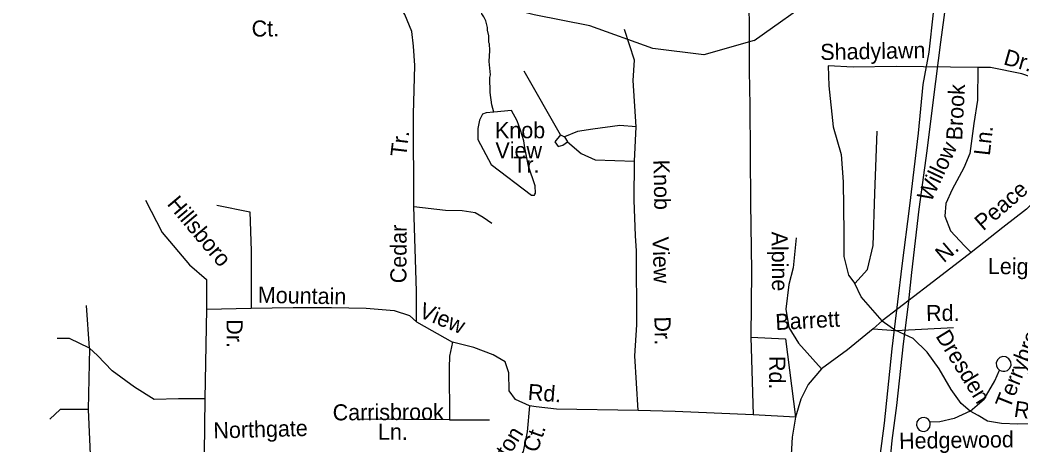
# Model space of a CAD drawing. Extents: x 1547597 to 1699558, y 810033 to 920809.
# Drawn here: x 1600245 to 1606161, y 855999 to 858511 of the extents above; entities that cross this region are included whole.
import ezdxf

# ---------------------------------------------------------------- set-up
doc = ezdxf.new("R2010")
doc.units = 0
for name, color, linetype in [('Exist Hydrographic Misc Water Feature', 7, 'Continuous'), ('Exist Road Non-System Type 51', 7, 'Continuous'), ('Exist Road Non-System Type 51 Label', 7, 'Continuous'), ('Exist Utilities Electrical Transmission Line', 7, 'Continuous')]:
    doc.layers.add(name, color=color, linetype=linetype)

msp = doc.modelspace()

# ---------------------------------------------------------------- linework, layer by layer
at = {"layer": 'Exist Hydrographic Misc Water Feature'}
for points in [[(1604584.3, 858390.6), (1604287.2, 858305.2), (1603985.1, 858343), (1603612.2, 858475.9), (1603283.5, 858542.3), (1603061.6, 858597.4), (1602912.6, 858649.7), (1602822.6, 858766.3), (1602649.1, 858955.8), (1602559.2, 859056.1), (1602486.9, 859102.3), (1602189.8, 859143.4), (1601995.6, 859301.8), (1601795.6, 859312.4), (1601299.5, 858990.5), (1600990.4, 858944.3), (1600488.8, 858943), (1600013.3, 858958.8), (1599039.8, 858996.7), (1598638.6, 858913.6)], [(1604584.3, 858390.6), (1604956.1, 858655.5), (1605784.2, 858699.8), (1606209.7, 858996.3)], [(1603044.7, 857966.8), (1603034.4, 858010.4), (1603023.4, 858082.5), (1603022.5, 858170.5), (1603024.8, 858186.4), (1603017.9, 858266.5), (1603020.8, 858330.5), (1603019.4, 858370.5), (1603015.5, 858378.5), (1603016, 858418.5), (1603008.4, 858450.6), (1603008.6, 858466.6), (1602997.2, 858506.8), (1602985.5, 858530.9), (1602973.7, 858547.1), (1602971.9, 858555.1), (1602912.6, 858649.7)], [(1603044.7, 857966.8), (1602999.4, 857962.8), (1602977.9, 857955.6), (1602960.2, 857918.7), (1602949.8, 857869.4), (1602949.9, 857804.2), (1603029.8, 857656.6), (1603267.6, 857476.7), (1603284.9, 857475.6), (1603287.7, 857481)], [(1603287.7, 857481), (1603290.9, 857487.1), (1603289.6, 857531.7), (1603249.7, 857647.5), (1603227.8, 857754.9), (1603221.7, 857797), (1603203.4, 857860.7), (1603182.6, 857916.2), (1603150.3, 857975.9), (1603044.7, 857966.8)]]:
    msp.add_lwpolyline(points, dxfattribs=at)
at = {"layer": 'Exist Road Non-System Type 51'}
for points in [[(1604523.8, 858949.4), (1604554.7, 858810.2), (1604551.3, 858642.4), (1604554.7, 858426.7), (1604554.7, 858211), (1604558.1, 858005.6), (1604561.4, 857430.5), (1604568.2, 857026.5), (1604564.6, 856637.2)], [(1602573.3, 857409.5), (1602570.3, 857954.4), (1602579.2, 858242.1), (1602570.3, 858356.4), (1602561.4, 858442.4), (1602519.9, 858543.3), (1602448.8, 858667.9), (1602410.3, 858724.2), (1602389.3, 858797.1)], [(1603885.6, 857879), (1603869.2, 858153.3), (1603877.4, 858274.1), (1603817.1, 858455.1)], [(1605021.5, 858240.6), (1605024.5, 858121.7), (1605049.7, 857879.1), (1605097.7, 857717.3), (1605110.3, 857555.6), (1605112.9, 857252.3), (1605112.9, 857112.6), (1605140.6, 857003.9), (1605178.6, 856953.3)], [(1605905.4, 858230.5), (1605423, 858235.6), (1605168, 858233), (1605021.5, 858240.6)], [(1605905.4, 858230.5), (1605902.8, 858038.4), (1605882.6, 857899.4), (1605857.4, 857722.5), (1605822, 857636.6), (1605753.8, 857510.2), (1605716, 857426.8), (1605710.9, 857351), (1605743.7, 857265.8), (1605827.1, 857177.4), (1605866.7, 857136.9)], [(1606563.5, 858048.4), (1606410.4, 858109.2), (1606165.5, 858192.6), (1605981.1, 858230.5), (1605905.4, 858230.5)], [(1603438.8, 857832.4), (1603225, 858208.2)], [(1603885.6, 857879), (1603789.7, 857887.2), (1603630.7, 857865.3), (1603540.2, 857851.6), (1603463.5, 857821.4)], [(1603877.5, 857677), (1603885.6, 857879)], [(1603438.8, 857832.4), (1603405.9, 857791.2), (1603425.1, 857763.8), (1603452.5, 857772), (1603479.9, 857791.2)], [(1603438.8, 857832.4), (1603463.5, 857821.4)], [(1603463.5, 857821.4), (1603479.9, 857791.2)], [(1605178.6, 856953.3), (1605254.3, 857036.7), (1605287.2, 857178.3), (1605297.3, 857486.6), (1605309.8, 857853.8)], [(1603479.9, 857791.2), (1603562.1, 857722.6), (1603644.4, 857684.2), (1603877.5, 857677)], [(1606429.7, 857727.4), (1606369, 857598.5), (1606285.7, 857484.8), (1606192.3, 857393.8), (1606053.4, 857285.1), (1605866.7, 857136.9)], [(1603898.5, 856203.6), (1603877.6, 856526.1), (1603891.3, 856709.9), (1603888.6, 857146.1), (1603883, 857235.3), (1603874.8, 857446.6), (1603877.5, 857677)], [(1600986.1, 857446.8), (1601086.1, 857255.3), (1601246.9, 857063.9), (1601346.9, 856976.9), (1601346.9, 856802.9)], [(1601407.8, 857416.3), (1601603.4, 857377.2), (1601612.1, 857146.6), (1601612.1, 856968.2), (1601612.1, 856807.3)], [(1602573.3, 857409.5), (1602758.8, 857388.1), (1602858.6, 857386.2), (1602934.4, 857372.7), (1602981.9, 857345.9), (1603033.2, 857311.1)], [(1602588.9, 856727.3), (1602588.1, 856908.3), (1602573.3, 857409.5)], [(1604832.5, 857223.8), (1604814.9, 857046.9), (1604789.6, 856948.3), (1604771.9, 856801.7), (1604789.6, 856693.1), (1604845.2, 856602.1), (1604981.5, 856450.4)], [(1605866.7, 857136.9), (1605617.9, 856945.8), (1605340.2, 856733.5)], [(1605340.2, 856733.5), (1605216.5, 856875), (1605178.6, 856953.3)], [(1600655.8, 856572.4), (1600638.4, 856824.7)], [(1601346.9, 856802.9), (1601338.2, 856272.2)], [(1601346.9, 856802.9), (1601612.1, 856807.3)], [(1601612.1, 856807.3), (1601859.8, 856811.6), (1602085.9, 856811.6), (1602290.2, 856807.3), (1602455.3, 856794.2), (1602546.6, 856763.8), (1602588.9, 856727.3)], [(1602588.9, 856727.3), (1602801.2, 856607)], [(1605287.2, 856685.4), (1605135.6, 856561.6), (1604981.5, 856450.4)], [(1605340.2, 856733.5), (1605287.2, 856685.4)], [(1605287.2, 856685.4), (1605421, 856675.3)], [(1605340.2, 856733.5), (1605421, 856675.3)], [(1605421, 856675.3), (1605761.9, 856693)], [(1600655.8, 856572.4), (1600538.4, 856628.9), (1600464.5, 856628.9)], [(1604564.6, 856637.2), (1604578.3, 856178.4)], [(1604564.6, 856637.2), (1604769.9, 856626.9)], [(1604769.9, 856626.9), (1604828.1, 856164.7)], [(1605859.4, 856198.9), (1605806.4, 856244.4), (1605748.3, 856327.8), (1605677.6, 856449.1), (1605606.9, 856547.7), (1605523.5, 856628.5), (1605421, 856675.3)], [(1600655.8, 856572.4), (1600647.8, 856208.1)], [(1601338.2, 856272.2), (1601181.7, 856272.2), (1601038.3, 856267.9), (1600920.9, 856341.8), (1600790.5, 856437.5), (1600703.6, 856528.9), (1600655.8, 856572.4)], [(1602801.2, 856607), (1602784.1, 856524.8), (1602780.7, 856456.3)], [(1603255.4, 856231), (1603174.1, 856268), (1603136.5, 856319.4), (1603133, 856425.5), (1603112.5, 856490.6), (1603040.7, 856531.6), (1602927.8, 856576.2), (1602801.2, 856607)], [(1606054.3, 856434.9), (1606065.3, 856435.2), (1606080.6, 856440.1), (1606093.9, 856453.3), (1606101.7, 856470.5), (1606100.5, 856490), (1606088.6, 856509.2), (1606071.8, 856519.8), (1606053.7, 856521.5), (1606035.9, 856515.7), (1606022.3, 856502.2), (1606014.1, 856485.9), (1606016.3, 856464.9), (1606023.6, 856450.9), (1606034.6, 856441.1), (1606043.9, 856436.7), (1606054.3, 856434.9)], [(1602780.7, 856456.3), (1602784.1, 856148.2)], [(1604981.5, 856450.4), (1604903.3, 856356.5), (1604858.8, 856270.9), (1604828.1, 856164.7)], [(1605859.4, 856198.9), (1605942.7, 856269.7), (1606005.9, 856378.3), (1606034.6, 856441.1)], [(1601338.2, 856272.2), (1601333.9, 855950.3)], [(1600647.8, 856208.1), (1600482.7, 856208.1), (1600421.8, 856151.6)], [(1600647.8, 856208.1), (1600660.9, 855899.3)], [(1603255.4, 856231), (1603241.7, 856076.9), (1603217.8, 855960.5), (1603125.4, 855803), (1603070.7, 855720.9)], [(1603898.5, 856203.6), (1603416.2, 856210.4), (1603296.4, 856224.1), (1603255.4, 856231)], [(1602784.1, 856148.2), (1602253.9, 856151.6)], [(1602784.1, 856148.2), (1603020.2, 856148.2)], [(1604116.2, 856197), (1603898.5, 856203.6)], [(1604578.3, 856178.4), (1604116.2, 856197)], [(1604828.1, 856164.7), (1604578.3, 856178.4)], [(1604828.1, 856164.7), (1604807.5, 856044.9), (1604800.7, 855908), (1604793.8, 855805.3), (1604779.6, 855729.1)], [(1605624.8, 856122.6), (1605623.8, 856133.3), (1605614.1, 856150.1), (1605601.7, 856158.7), (1605588.8, 856162.2), (1605571.9, 856160.3), (1605556.3, 856152.3), (1605545.2, 856136.3), (1605542.6, 856117.1), (1605548.1, 856101.6), (1605559.8, 856087.9), (1605574.3, 856081.2), (1605589.7, 856079.9), (1605608.7, 856087.8), (1605621.4, 856104.1), (1605624.8, 856122.6)], [(1605859.4, 856198.9), (1605766, 856155.9), (1605680.1, 856135.7), (1605623.8, 856133.3)], [(1606483.2, 856120.8), (1606314, 856125.6), (1606142.2, 856123.1), (1606046.3, 856125.6), (1605962.9, 856140.8), (1605907.4, 856173.6), (1605859.4, 856198.9)]]:
    msp.add_lwpolyline(points, dxfattribs=at)
at = {"layer": 'Exist Utilities Electrical Transmission Line'}
for points in [[(1606188.9, 862441.7), (1606114.6, 862291), (1606083.3, 862079.7), (1606035.2, 861688.6), (1605980.2, 861255.7), (1605918.3, 860753.1), (1605862.5, 860386.2), (1605838.3, 860120.8), (1605807.3, 859925.3), (1605778.9, 859647.9), (1605735, 859282.8), (1605693.8, 858949.6), (1605641.6, 858552.9), (1605615.9, 858321.3), (1605581, 858130.1), (1605552.3, 857842.7), (1605501.6, 857413.7), (1605456, 857058.6), (1605430.6, 856845.2), (1605398.2, 856567.9), (1605351.3, 856128.8), (1605317, 855857.5)], [(1606162.9, 862184.3), (1606142.1, 862018.9), (1606108.1, 861763.4), (1606070.9, 861428.2), (1606024.2, 861011.3), (1605966, 860608.4), (1605930.4, 860381), (1605900.4, 860123.7), (1605877.4, 859938.3), (1605836.3, 859619.1), (1605791.5, 859184), (1605732.8, 858767.1), (1605714.2, 858599.6), (1605684.7, 858380.1), (1605641.4, 858039.2), (1605604.6, 857737.8), (1605557.2, 857392.7), (1605513.2, 857019.8), (1605494.2, 856832.1), (1605464.6, 856596.8), (1605424.8, 856233.6), (1605397.6, 856026.2), (1605383.2, 855880.4)]]:
    msp.add_lwpolyline(points, dxfattribs=at)

# ---------------------------------------------------------------- texts
at = {"layer": 'Exist Road Non-System Type 51 Label'}
for s, rotation, p in [('Ct.', 0.54267, (1601614.4, 858413.1)), ('Shadylawn', 1.11106, (1604975.4, 858274.5)), ('Dr.', 344.02466, (1606052.2, 858250.4)), ('Brook', 87.05035, (1605812.9, 857798.6)), ('Knob', 359.89022, (1603051.8, 857812.7)), ('Ln.', 83.54536, (1605976.1, 857706.7)), ('Tr.', 83.35037, (1602528, 857699.4)), ('View', 359.89022, (1603054.6, 857693.5)), ('Willow', 64.65638, (1605629.2, 857430.3)), ('Tr.', 359.89022, (1603159.8, 857608.5)), ('Knob', 271.11603, (1603988.2, 857684.8)), ('Peace', 40.81144, (1605937.3, 857261.3)), ('Hillsboro', 310.1093, (1601109.7, 857422)), ('Cedar', 89.71385, (1602528.5, 856955.1)), ('View', 271.72591, (1603982.8, 857228.9)), ('Alpine', 270.49901, (1604686.3, 857260.4)), ('N.', 40.09312, (1605704.1, 857072.7)), ('Leighton', 359.08712, (1605964.5, 857010.6)), ('Mountain', 358.92491, (1601650, 856839.9)), ('View', 337.81998, (1602596, 856757.3)), ('Rd.', 0.44815, (1605600, 856731.4)), ('Terrybrook', 68.24893, (1606094.1, 856208.2)), ('Dr.', 270.87633, (1603994.3, 856758.3)), ('Barrett', 3.13245, (1604711.7, 856678.2)), ('Dr.', 270.63216, (1601465.3, 856741.9)), ('Dresden', 301.51151, (1605653.4, 856643.3)), ('Rd.', 269.38385, (1604673.6, 856525.9)), ('Rd.', 355.54991, (1603243.5, 856266.3)), ('Carrisbrook', 0.36204, (1602093.2, 856144.5)), ('Rd.', 351.54174, (1606114.8, 856167.4)), ('Northgate', 1.57444, (1601389.1, 856037.4)), ('Ln.', 359.68118, (1602360.3, 856030.5)), ('Braxton', 58.1444, (1602992.4, 855697.9)), ('Ct.', 71.15273, (1603301.8, 855949.4)), ('Hedgewood', 0.83344, (1605440.8, 855976.3))]:
    msp.add_text(s, height=95, rotation=rotation, dxfattribs=at).set_placement(p)

doc.saveas('drawing.dxf')
